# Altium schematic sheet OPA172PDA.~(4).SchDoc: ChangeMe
size 431 x 279 mm; Date: Not shown in title block; ApprovedBy: Not shown in title block; CheckedBy: Not shown in title block; Author: Not shown in title block; CompanyName: Not shown in title block; DrawnBy: Enter Full Name; Engineer: Not shown in title block; Organization: Not shown in title block; Address1: Not shown in title block; Address2: Not shown in title block; Address3: Not shown in title block; Address4: Not shown in title block; DocumentNumber: 2; Revision: Use project parameter SCH_Rev; SheetNumber: 2; SheetTotal: 3; PageSetup: Record=PageOptions|CenterHorizontal=True|CenterVertical=True|PrintScale=1.00|XCorrection=1.00|YCorrection=1.00|PrintKind=0|BorderSize=5000000|LeftOffset=0|BottomOffset=0|Orientation=2|PaperLength=1000|PaperWidth=1000|Scale=100|PaperSource=15|PrintQuality=600|MediaType=1|DitherType=10|PaperKind=Letter|PrintScaleMode=1
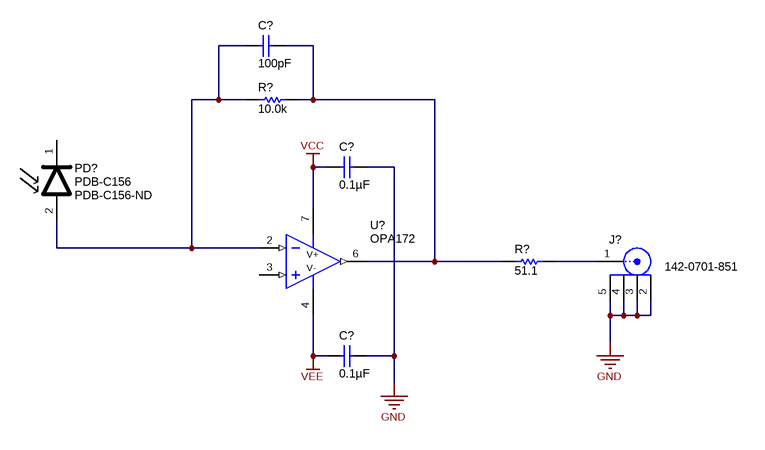
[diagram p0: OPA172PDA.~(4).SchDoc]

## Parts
(Parts that share a designator on the sheet are numbered #1, #2 ... from top to bottom, then left to right.)
C?#1  ValueDisplayed: 100pF  [0603]  (hidden comment: 06033C101KAT2A)
C?#2  ValueDisplayed: 0.1µF  [0603]  (hidden comment: 0603YC104JAT2A)
C?#3  ValueDisplayed: 0.1µF  [0603]  (hidden comment: 0603YC104JAT2A)
J?  142-0701-851  [Emerson_142-0701-851]
PD?  PDB-C156  Supplier Part Number 1: PDB-C156-ND  [PDB-C156]
R?#1  value 10.0k  [0603]  (hidden comment: CRCW060310K0FKEA)
R?#2  value 51.1  [0603]  (hidden comment: CRCW060351R1FKEA)
U?  OPA172  [M08A_M]

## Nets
GND: C?#2.1 C?#3.1 J?.2 J?.3 J?.4 J?.5
VCC: C?#2.2 U?.7(V+)
VEE: C?#3.2 U?.4(V-)
NetC?#1_1: C?#1.1 R?#1.2 R?#2.1 U?.6(OUT)
NetC?#1_2: C?#1.2 PD?.2(A) R?#1.1 U?.2(IN-)
NetJ?_1: J?.1 R?#2.2

Not connected (* = marked no-connect by the designer): PD? 1(C); U? 3(IN+)

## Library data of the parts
C?#1 = 06033C101KAT2A: CAP, CERM, 100pF, 25V, +/-10%, X7R, 0603; Manufacturer: AVX; Polarized: N; CompType: Capacitor; U/M: EA; Cap_F: 0.0000000001; Tolerance_%: 10; VDC_V: 25; TaMin_C: -55; TaMax_C: 125
C?#2 C?#3 = 0603YC104JAT2A: CAP, CERM, 0.1uF, 16V, +/-5%, X7R, 0603; Manufacturer: AVX; Polarized: N; CompType: Capacitor; U/M: EA; Cap_F: 0.0000001; Tolerance_%: 5; ESR_Ohm: 0.039; Value1: 0.039 ohm; VDC_V: 16; TaMin_C: -55; TaMax_C: 125
J? = 142-0701-851: Connector, SMT, End launch SMA 50 ohm; Manufacturer: Emerson Network Power; Alternate Manufacturer: Any; Alternate PartNumber: Equivalent; U/M: EA
PD? = PDB-C156: Photodiode; Manufacturer: Used in BOM report; SymbolVersion: use current date i.e. 2008-05-20; SymbolCreator: Use LDAP id; CompType: Used in some BOM reports.  Useful for finding later.; U/M: EA, IN, or GM
R?#1 = CRCW060310K0FKEA: RES, 10.0k ohm, 1%, 0.1W, 0603; Manufacturer: Vishay-Dale; Alternate Manufacturer: Any; Alternate PartNumber: Equivalent; CompType: Resistor; Res_ohm: 10000; Value_Code: 10k0; Tolerance_%: 1; Power_W: 0.1; VDC_V: 75; TempCo: 100 ppm/C; EIA_Code: E96; U/M: EA
R?#2 = CRCW060351R1FKEA: RES, 51.1 ohm, 1%, 0.1W, 0603; Manufacturer: Vishay-Dale; Alternate Manufacturer: Any; Alternate PartNumber: Equivalent; CompType: Resistor; Value_Code: 51R1; Tolerance_%: 1; Power_W: 0.1; VDC_V: 75; TempCo: 100 ppm/C; EIA_Code: E96; U/M: EA
U? = OPA172: Manufacturer: Used in BOM report; SymbolVersion: use current date i.e. 2008-05-20; SymbolCreator: Use LDAP id; CompType: Used in some BOM reports.  Useful for finding later.; U/M: EA, IN, or GM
